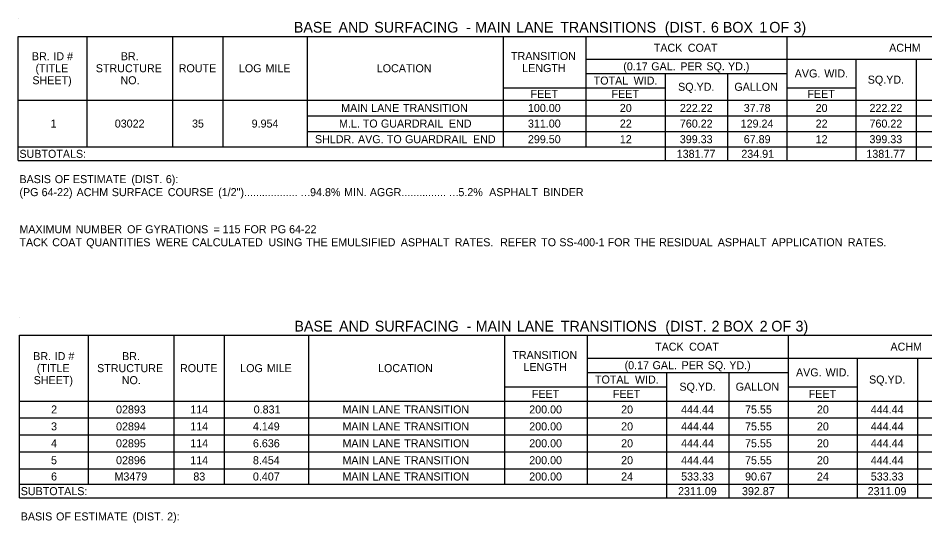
# Model space of a CAD drawing. Extents: x 542596 to 1930787, y -1948294 to 596640.
# Drawn here: x 548345 to 549024, y -1946541 to -1946163 of the extents above; entities that cross this region are included whole.
import ezdxf

# ---------------------------------------------------------------- set-up
doc = ezdxf.new("R2010")
doc.units = 0
doc.layers.add('Default', color=7, linetype='Continuous')

msp = doc.modelspace()

# ---------------------------------------------------------------- linework, layer by layer
at = {"layer": 'Default'}
for p, q in [((548344.61, -1946162.92), (548344.61, -1946162.92)), ((548344.61, -1946176.57), (549201.63, -1946176.57)), ((548344.61, -1946269.68), (548344.61, -1946176.57)), ((548396.28, -1946224.35), (548396.28, -1946176.57)), ((548396.28, -1946259.45), (548396.28, -1946176.57)), ((548460.63, -1946259.45), (548460.63, -1946176.57)), ((548498.17, -1946259.45), (548498.17, -1946176.57)), ((548561.54, -1946259.45), (548561.54, -1946176.57)), ((548708.28, -1946259.45), (548708.28, -1946176.57)), ((548770.19, -1946259.45), (548770.19, -1946176.57)), ((548920.83, -1946193.63), (548920.83, -1946176.57)), ((548920.83, -1946269.68), (548920.83, -1946176.57)), ((548770.19, -1946193.63), (549201.63, -1946193.63)), ((548972.51, -1946193.63), (549017.84, -1946193.63)), ((548972.51, -1946269.68), (548972.51, -1946193.63)), ((549017.84, -1946269.68), (549017.84, -1946193.63)), ((548770.19, -1946204.36), (548920.83, -1946204.36)), ((548829.67, -1946269.68), (548829.67, -1946204.36)), ((548876.47, -1946269.68), (548876.47, -1946204.36)), ((548708.28, -1946215.08), (548770.19, -1946215.08)), ((548708.28, -1946215.08), (548829.67, -1946215.08)), ((548829.67, -1946224.35), (548829.67, -1946215.08)), ((548920.83, -1946215.08), (548972.51, -1946215.08)), ((548920.83, -1946224.35), (548920.83, -1946215.08)), ((548972.51, -1946224.35), (548972.51, -1946215.08)), ((548344.61, -1946224.35), (549201.63, -1946224.35)), ((548829.67, -1946224.35), (548920.83, -1946224.35)), ((548920.83, -1946224.35), (549201.63, -1946224.35)), ((548561.54, -1946236.05), (549201.63, -1946236.05)), ((548920.83, -1946269.68), (548920.83, -1946236.05)), ((548972.51, -1946269.68), (548972.51, -1946236.05)), ((549017.84, -1946269.68), (549017.84, -1946236.05)), ((548561.54, -1946247.75), (549081.71, -1946247.75)), ((548561.54, -1946247.75), (549017.84, -1946247.75)), ((549017.84, -1946247.75), (549201.63, -1946247.75)), ((548344.61, -1946259.45), (549201.63, -1946259.45)), ((548829.67, -1946269.68), (548829.67, -1946259.45)), ((548344.61, -1946269.68), (549201.63, -1946269.68)), ((548345.58, -1946386.84), (548345.58, -1946386.84)), ((548345.58, -1946400.49), (549202.61, -1946400.49)), ((548345.58, -1946522.36), (548345.58, -1946400.49)), ((548397.26, -1946512.13), (548397.26, -1946400.49)), ((548461.61, -1946512.13), (548461.61, -1946400.49)), ((548499.14, -1946512.13), (548499.14, -1946400.49)), ((548562.52, -1946512.13), (548562.52, -1946400.49)), ((548709.26, -1946512.13), (548709.26, -1946400.49)), ((548771.17, -1946512.13), (548771.17, -1946400.49)), ((548921.81, -1946417.55), (548921.81, -1946400.49)), ((548921.81, -1946522.36), (548921.81, -1946400.49)), ((548771.17, -1946417.55), (549202.61, -1946417.55)), ((548973.48, -1946417.55), (549018.82, -1946417.55)), ((548973.48, -1946522.36), (548973.48, -1946417.55)), ((549018.82, -1946522.36), (549018.82, -1946417.55)), ((548771.17, -1946428.28), (548921.81, -1946428.28)), ((548830.64, -1946522.36), (548830.64, -1946428.28)), ((548877.44, -1946522.36), (548877.44, -1946428.28)), ((548709.26, -1946439), (548771.17, -1946439)), ((548709.26, -1946439), (548830.64, -1946439)), ((548830.64, -1946449.73), (548830.64, -1946439)), ((548921.81, -1946439), (548973.48, -1946439)), ((548921.81, -1946449.73), (548921.81, -1946439)), ((548973.48, -1946449.73), (548973.48, -1946439)), ((548345.58, -1946449.73), (549202.61, -1946449.73)), ((548830.64, -1946449.73), (548921.81, -1946449.73)), ((548921.81, -1946449.73), (549202.61, -1946449.73)), ((548345.58, -1946462.4), (549202.61, -1946462.4)), ((548562.52, -1946462.4), (549202.61, -1946462.4)), ((548345.58, -1946475.08), (549202.61, -1946475.08)), ((548562.52, -1946475.08), (549202.61, -1946475.08)), ((548345.58, -1946487.75), (549202.61, -1946487.75)), ((548562.52, -1946487.75), (549202.61, -1946487.75)), ((548345.58, -1946500.43), (549202.61, -1946500.43)), ((548397.26, -1946512.13), (548397.26, -1946500.43)), ((548461.61, -1946512.13), (548461.61, -1946500.43)), ((548499.14, -1946512.13), (548499.14, -1946500.43)), ((548562.52, -1946500.43), (549202.61, -1946500.43)), ((548562.52, -1946512.13), (548562.52, -1946500.43)), ((548345.58, -1946512.13), (549202.61, -1946512.13)), ((548562.52, -1946512.13), (549202.61, -1946512.13)), ((548830.64, -1946522.36), (548830.64, -1946512.13)), ((548921.81, -1946522.36), (548921.81, -1946512.13)), ((548973.48, -1946522.36), (548973.48, -1946512.13)), ((549018.82, -1946522.36), (549018.82, -1946512.13)), ((548345.58, -1946522.36), (549202.61, -1946522.36))]:
    msp.add_line(p, q, dxfattribs=at)

# ---------------------------------------------------------------- texts
for s, height, p in [('BASE', 8, (548551.19, -1946173.75)), (' AND', 8, (548581.69, -1946173.75)), (' SURFACING', 8, (548608.46, -1946173.75)), (' MAIN', 8, (548684.08, -1946173.75)), (' LANE', 8, (548714.85, -1946173.75)), (' TRANSITIONS', 8, (548747.83, -1946173.75)), (' (DIST.', 8, (548826.16, -1946173.75)), (' 6', 8, (548860.78, -1946173.75)), (' BOX', 8, (548869.7, -1946173.75)), (' 1', 8, (548897.02, -1946173.75)), (' OF', 8, (548904.52, -1946173.75)), (' 3)', 8, (548922.63, -1946173.75)), (' -', 8, (548677.34, -1946173.75)), ('BR.', 6, (548354.92, -1946194.46)), (' ID', 6, (548368.78, -1946194.46)), (' #', 6, (548379.08, -1946194.46)), ('BR.', 6, (548421.53, -1946194.46)), ('TRANSITION', 6, (548713.96, -1946194.33)), ('TACK', 6, (548820.92, -1946188.1)), (' COAT', 6, (548844.2, -1946188.1)), ('ACHM', 6, (548997.3, -1946188.1)), ('(TITLE', 6, (548357.61, -1946203.46)), ('STRUCTURE', 6, (548402.81, -1946203.46)), ('ROUTE', 6, (548464.94, -1946203.46)), ('LOG', 6, (548510.06, -1946203.46)), (' MILE', 6, (548527.72, -1946203.46)), ('LOCATION', 6, (548613.36, -1946203.46)), ('LENGTH', 6, (548722.33, -1946203.33)), ('(0.17', 6, (548798.07, -1946202)), (' GAL.', 6, (548816.8, -1946202)), (' PER', 6, (548838.58, -1946202)), (' SQ.', 6, (548858.1, -1946202)), (' YD.)', 6, (548874.3, -1946202)), ('AVG.', 6, (548926.52, -1946207.36)), (' WID.', 6, (548946.44, -1946207.36)), ('SHEET)', 6, (548355.29, -1946212.46)), ('NO.', 6, (548421.29, -1946212.46)), ('TOTAL', 6, (548775.9, -1946212.72)), (' WID.', 6, (548803.59, -1946212.72)), ('SQ.YD.', 6, (548981.25, -1946211.99)), ('SQ.YD.', 6, (548839.15, -1946217.35)), ('GALLON', 6, (548881.29, -1946217.35)), ('FEET', 6, (548728.61, -1946222.71)), ('FEET', 6, (548789.3, -1946222.71)), ('FEET', 6, (548936.04, -1946222.71)), ('MAIN', 6, (548586.68, -1946233.2)), (' LANE', 6, (548606.95, -1946233.2)), (' TRANSITION', 6, (548630.73, -1946233.2)), ('100.00', 6, (548726.62, -1946233.2)), ('20', 6, (548795.47, -1946233.2)), ('222.22', 6, (548840.48, -1946233.2)), ('37.78', 6, (548888.35, -1946233.2)), ('20', 6, (548942.21, -1946233.2)), ('222.22', 6, (548982.58, -1946233.2)), ('1', 6, (548368.88, -1946244.9)), ('03022', 6, (548417.03, -1946244.9)), ('35', 6, (548474.91, -1946244.9)), ('9.954', 6, (548519.58, -1946244.9)), ('M.L.', 6, (548585.07, -1946244.9)), (' TO', 6, (548600.63, -1946244.9)), (' GUARDRAIL', 6, (548614.23, -1946244.9)), (' END', 6, (548665.18, -1946244.9)), ('311.00', 6, (548726.62, -1946244.9)), ('22', 6, (548795.49, -1946244.9)), ('760.22', 6, (548840.48, -1946244.9)), ('129.24', 6, (548886.04, -1946244.9)), ('22', 6, (548942.23, -1946244.9)), ('760.22', 6, (548982.58, -1946244.9)), ('SHLDR.', 6, (548567.03, -1946256.6)), (' AVG.', 6, (548597.04, -1946256.6)), (' TO', 6, (548618.67, -1946256.6)), (' GUARDRAIL', 6, (548632.27, -1946256.6)), (' END', 6, (548683.21, -1946256.6)), ('299.50', 6, (548726.62, -1946256.6)), ('12', 6, (548795.49, -1946256.6)), ('399.33', 6, (548840.44, -1946256.6)), ('67.89', 6, (548888.35, -1946256.6)), ('12', 6, (548942.23, -1946256.6)), ('399.33', 6, (548982.55, -1946256.6)), ('SUBTOTALS:', 6, (548345.58, -1946267.56)), ('1381.77', 6, (548838.11, -1946267.56)), ('234.91', 6, (548886.52, -1946267.56)), ('1381.77', 6, (548980.22, -1946267.56)), ('BASIS', 6, (548345.58, -1946286.52)), (' OF', 6, (548369.84, -1946286.52)), (' ESTIMATE', 6, (548383.43, -1946286.52)), (' (DIST.', 6, (548427.24, -1946286.52)), (' 6):', 6, (548453.05, -1946286.52)), ('(PG', 6, (548345.58, -1946296.27)), (' 64-22)', 6, (548359.96, -1946296.27)), (' ACHM', 6, (548386.2, -1946296.27)), (' SURFACE', 6, (548412.59, -1946296.27)), (' COURSE', 6, (548454.53, -1946296.27)), (' (1/2")..................', 6, (548492.28, -1946296.27)), ('94.8%', 6, (548563.38, -1946296.27)), (' MIN.', 6, (548586.62, -1946296.27)), (' AGGR...............', 6, (548605.91, -1946296.27)), ('5.2%', 6, (548674.52, -1946296.27)), ('  ASPHALT', 6, (548693.1, -1946296.27)), (' BINDER', 6, (548735.79, -1946296.27)), ('…', 6, (548555.98, -1946296.27)), ('…', 6, (548667.12, -1946296.27)), ('MAXIMUM', 6, (548345.58, -1946324.06)), (' NUMBER', 6, (548385.47, -1946324.06)), (' OF', 6, (548424.02, -1946324.06)), (' GYRATIONS', 6, (548437.6, -1946324.06)), (' =', 6, (548488.87, -1946324.06)), (' 115', 6, (548495.63, -1946324.06)), (' FOR', 6, (548511.6, -1946324.06)), (' PG', 6, (548531.51, -1946324.06)), (' 64-22', 6, (548545.43, -1946324.06)), ('TACK', 6, (548345.58, -1946333.81)), (' COAT', 6, (548367.93, -1946333.81)), (' QUANTITIES', 6, (548393.38, -1946333.81)), (' WERE', 6, (548445.57, -1946333.81)), (' CALCULATED', 6, (548472.61, -1946333.81)), (' USING', 6, (548529.93, -1946333.81)), (' THE', 6, (548558.28, -1946333.81)), (' EMULSIFIED', 6, (548576.93, -1946333.81)), (' ASPHALT', 6, (548629.12, -1946333.81)), (' RATES.', 6, (548669.49, -1946333.81)), ('  REFER', 6, (548701.37, -1946333.81)), (' TO', 6, (548734.32, -1946333.81)), (' SS-400-1', 6, (548747.92, -1946333.81)), (' FOR', 6, (548784.11, -1946333.81)), (' THE', 6, (548804.02, -1946333.81)), (' RESIDUAL', 6, (548822.67, -1946333.81)), (' ASPHALT', 6, (548866.63, -1946333.81)), (' APPLICATION', 6, (548907, -1946333.81)), (' RATES.', 6, (548964.08, -1946333.81)), ('BASE', 8, (548551.62, -1946397.66)), (' AND', 8, (548582.12, -1946397.66)), (' SURFACING', 8, (548608.89, -1946397.66)), (' MAIN', 8, (548684.52, -1946397.66)), (' LANE', 8, (548715.28, -1946397.66)), (' TRANSITIONS', 8, (548748.27, -1946397.66)), (' (DIST.', 8, (548826.59, -1946397.66)), (' 2', 8, (548861.21, -1946397.66)), (' BOX', 8, (548869.97, -1946397.66)), (' 2', 8, (548897.28, -1946397.66)), (' OF', 8, (548906.04, -1946397.66)), (' 3)', 8, (548924.15, -1946397.66)), (' -', 8, (548677.77, -1946397.66)), ('TACK', 6, (548821.9, -1946412.02)), (' COAT', 6, (548845.17, -1946412.02)), ('ACHM', 6, (548998.27, -1946412.02)), ('TRANSITION', 6, (548714.93, -1946418.25)), ('BR.', 6, (548355.9, -1946419.11)), (' ID', 6, (548369.76, -1946419.11)), (' #', 6, (548380.05, -1946419.11)), ('BR.', 6, (548422.5, -1946419.11)), ('(0.17', 6, (548799.05, -1946425.91)), (' YD.)', 6, (548875.27, -1946425.91)), ('(TITLE', 6, (548358.59, -1946428.11)), ('STRUCTURE', 6, (548403.79, -1946428.11)), ('ROUTE', 6, (548465.91, -1946428.11)), ('LOG', 6, (548511.03, -1946428.11)), (' MILE', 6, (548528.69, -1946428.11)), ('LOCATION', 6, (548614.33, -1946428.11)), ('LENGTH', 6, (548723.3, -1946427.25)), (' GAL.', 6, (548817.77, -1946425.91)), (' PER', 6, (548839.55, -1946425.91)), (' SQ.', 6, (548859.08, -1946425.91)), ('AVG.', 6, (548927.5, -1946431.28)), (' WID.', 6, (548947.42, -1946431.28)), ('SHEET)', 6, (548356.26, -1946437.11)), ('NO.', 6, (548422.27, -1946437.11)), ('TOTAL', 6, (548776.87, -1946436.64)), (' WID.', 6, (548804.57, -1946436.64)), ('SQ.YD.', 6, (548982.23, -1946436.64)), ('SQ.YD.', 6, (548840.12, -1946442)), ('GALLON', 6, (548882.26, -1946442)), ('FEET', 6, (548729.58, -1946447.36)), ('FEET', 6, (548790.28, -1946447.36)), ('FEET', 6, (548937.02, -1946447.36)), ('2', 6, (548369.31, -1946459.06)), ('02893', 6, (548417.97, -1946459.06)), ('114', 6, (548473.59, -1946459.06)), ('0.831', 6, (548521.12, -1946459.06)), ('MAIN', 6, (548587.65, -1946459.06)), (' LANE', 6, (548607.93, -1946459.06)), (' TRANSITION', 6, (548631.71, -1946459.06)), ('200.00', 6, (548727.6, -1946459.06)), ('20', 6, (548796.45, -1946459.06)), ('444.44', 6, (548841.43, -1946459.06)), ('75.55', 6, (548889.31, -1946459.06)), ('20', 6, (548943.19, -1946459.06)), ('444.44', 6, (548983.54, -1946459.06)), ('3', 6, (548369.28, -1946471.74)), ('02894', 6, (548417.98, -1946471.74)), ('114', 6, (548473.59, -1946471.74)), ('4.149', 6, (548520.53, -1946471.74)), ('MAIN', 6, (548587.65, -1946471.74)), (' LANE', 6, (548607.93, -1946471.74)), (' TRANSITION', 6, (548631.71, -1946471.74)), ('200.00', 6, (548727.6, -1946471.74)), ('20', 6, (548796.45, -1946471.74)), ('444.44', 6, (548841.43, -1946471.74)), ('75.55', 6, (548889.31, -1946471.74)), ('20', 6, (548943.19, -1946471.74)), ('444.44', 6, (548983.54, -1946471.74)), ('4', 6, (548369.29, -1946484.41)), ('02895', 6, (548417.95, -1946484.41)), ('114', 6, (548473.59, -1946484.41)), ('6.636', 6, (548520.54, -1946484.41)), ('MAIN', 6, (548587.65, -1946484.41)), (' LANE', 6, (548607.93, -1946484.41)), (' TRANSITION', 6, (548631.71, -1946484.41)), ('200.00', 6, (548727.6, -1946484.41)), ('20', 6, (548796.45, -1946484.41)), ('444.44', 6, (548841.43, -1946484.41)), ('75.55', 6, (548889.31, -1946484.41)), ('20', 6, (548943.19, -1946484.41)), ('444.44', 6, (548983.54, -1946484.41)), ('5', 6, (548369.26, -1946497.09)), ('02896', 6, (548417.97, -1946497.09)), ('114', 6, (548473.59, -1946497.09)), ('8.454', 6, (548520.55, -1946497.09)), ('MAIN', 6, (548587.65, -1946497.09)), (' LANE', 6, (548607.93, -1946497.09)), (' TRANSITION', 6, (548631.71, -1946497.09)), ('200.00', 6, (548727.6, -1946497.09)), ('20', 6, (548796.45, -1946497.09)), ('444.44', 6, (548841.43, -1946497.09)), ('75.55', 6, (548889.31, -1946497.09)), ('20', 6, (548943.19, -1946497.09)), ('444.44', 6, (548983.54, -1946497.09)), ('6', 6, (548369.28, -1946509.28)), ('M3479', 6, (548416.8, -1946509.28)), ('83', 6, (548475.9, -1946509.28)), ('0.407', 6, (548520.54, -1946509.28)), ('MAIN', 6, (548587.65, -1946509.28)), (' LANE', 6, (548607.93, -1946509.28)), (' TRANSITION', 6, (548631.71, -1946509.28)), ('200.00', 6, (548727.6, -1946509.28)), ('24', 6, (548796.45, -1946509.28)), ('533.33', 6, (548841.42, -1946509.28)), ('90.67', 6, (548889.33, -1946509.28)), ('24', 6, (548943.19, -1946509.28)), ('533.33', 6, (548983.53, -1946509.28)), ('SUBTOTALS:', 6, (548346.56, -1946520.25)), ('2311.09', 6, (548839.09, -1946520.25)), ('392.87', 6, (548887, -1946520.25)), ('2311.09', 6, (548981.2, -1946520.25)), ('BASIS', 6, (548346.56, -1946539.2)), (' OF', 6, (548370.82, -1946539.2)), (' ESTIMATE', 6, (548384.4, -1946539.2)), (' (DIST.', 6, (548428.21, -1946539.2)), (' 2):', 6, (548454.02, -1946539.2))]:
    msp.add_text(s, height=height, dxfattribs=at).set_placement(p)

doc.saveas('drawing.dxf')
